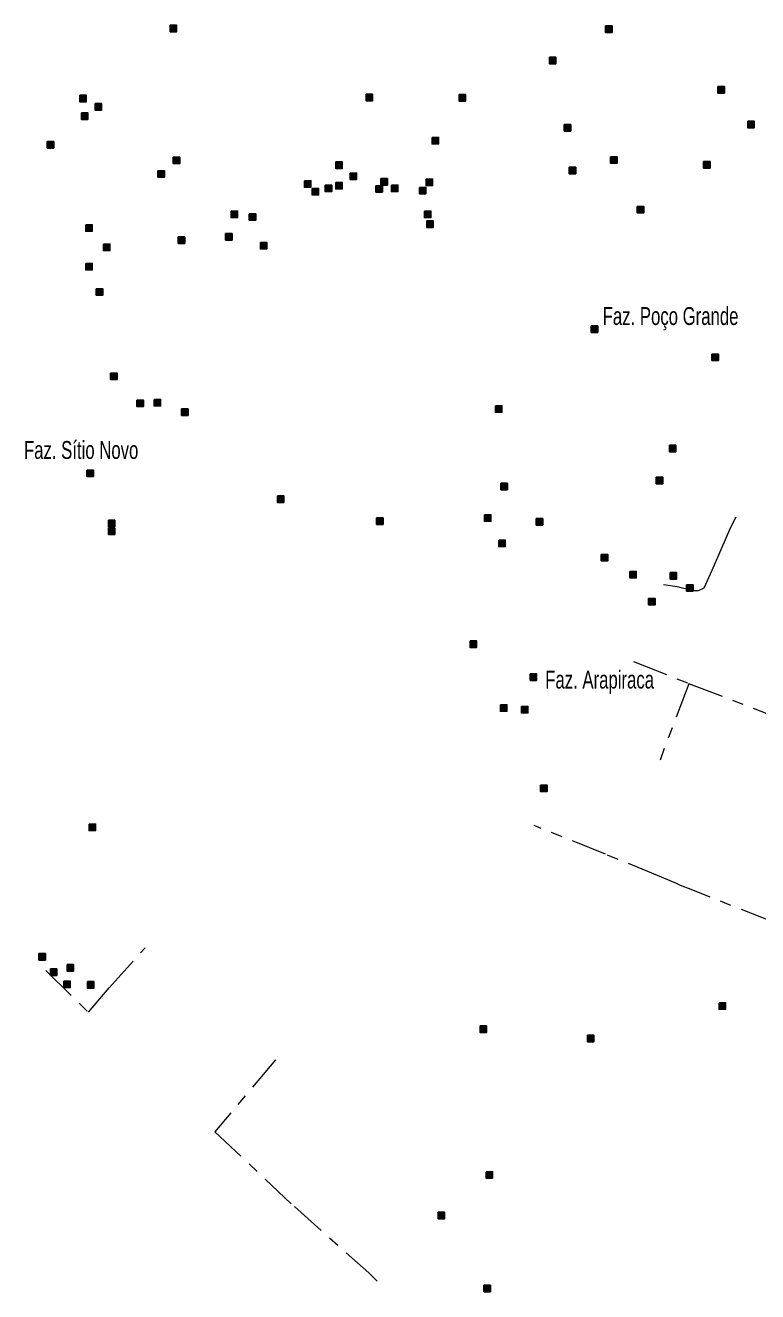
# Model space of a CAD drawing. Extents: x 445.4 to 500, y 8728.7 to 8784.
# Drawn here: x 486.04 to 492.59, y 8746.28 to 8757.61 of the extents above; entities that cross this region are included whole.
import ezdxf

# ---------------------------------------------------------------- set-up
doc = ezdxf.new("R2010")
doc.units = 0
doc.header["$LTSCALE"] = 0.064
doc.linetypes.add('DOT_DASHED', pattern=[7.7, 5, -1.2, 0.3, -1.2])
doc.layers.add('2', color=7, linetype='Continuous', lineweight=25)
doc.layers.add('22', color=7, linetype='DOT_DASHED', lineweight=13)
doc.layers.add('61', color=7, linetype='Continuous')

msp = doc.modelspace()

# ---------------------------------------------------------------- hatches: boundary and pattern name
at = {"layer": '2'}
for points in [[(487.3313, 8757.6084), (487.3893, 8757.6084), (487.3893, 8757.5504), (487.3313, 8757.5504)], [(491.2303, 8757.6032), (491.2883, 8757.6032), (491.2883, 8757.5452), (491.2303, 8757.5452)], [(490.7276, 8757.3221), (490.7856, 8757.3221), (490.7856, 8757.2641), (490.7276, 8757.2641)], [(492.2359, 8757.0607), (492.2939, 8757.0607), (492.2939, 8757.0027), (492.2359, 8757.0027)], [(486.5229, 8756.9821), (486.5809, 8756.9821), (486.5809, 8756.9241), (486.5229, 8756.9241)], [(486.6609, 8756.9081), (486.7189, 8756.9081), (486.7189, 8756.8501), (486.6609, 8756.8501)], [(489.0861, 8756.9919), (489.1441, 8756.9919), (489.1441, 8756.9339), (489.0861, 8756.9339)], [(489.9192, 8756.9888), (489.9772, 8756.9888), (489.9772, 8756.9308), (489.9192, 8756.9308)], [(486.5377, 8756.8242), (486.5957, 8756.8242), (486.5957, 8756.7662), (486.5377, 8756.7662)], [(490.8606, 8756.7205), (490.9186, 8756.7205), (490.9186, 8756.6625), (490.8606, 8756.6625)], [(492.5021, 8756.7501), (492.5601, 8756.7501), (492.5601, 8756.6921), (492.5021, 8756.6921)], [(486.2321, 8756.5678), (486.2901, 8756.5678), (486.2901, 8756.5098), (486.2321, 8756.5098)], [(489.6776, 8756.605), (489.7356, 8756.605), (489.7356, 8756.547), (489.6776, 8756.547)], [(487.3609, 8756.4297), (487.4189, 8756.4297), (487.4189, 8756.3717), (487.3609, 8756.3717)], [(488.815, 8756.3853), (488.873, 8756.3853), (488.873, 8756.3273), (488.815, 8756.3273)], [(490.905, 8756.3387), (490.963, 8756.3387), (490.963, 8756.2807), (490.905, 8756.2807)], [(491.2747, 8756.4324), (491.3327, 8756.4324), (491.3327, 8756.3744), (491.2747, 8756.3744)], [(492.1075, 8756.3889), (492.1655, 8756.3889), (492.1655, 8756.3309), (492.1075, 8756.3309)], [(487.2228, 8756.3064), (487.2808, 8756.3064), (487.2808, 8756.2484), (487.2228, 8756.2484)], [(488.534, 8756.2176), (488.592, 8756.2176), (488.592, 8756.1596), (488.534, 8756.1596)], [(488.9431, 8756.2867), (489.0011, 8756.2867), (489.0011, 8756.2287), (488.9431, 8756.2287)], [(489.2192, 8756.2374), (489.2772, 8756.2374), (489.2772, 8756.1794), (489.2192, 8756.1794)], [(489.6234, 8756.2324), (489.6814, 8756.2324), (489.6814, 8756.1744), (489.6234, 8756.1744)], [(488.603, 8756.1486), (488.661, 8756.1486), (488.661, 8756.0906), (488.603, 8756.0906)], [(488.7213, 8756.1782), (488.7793, 8756.1782), (488.7793, 8756.1202), (488.7213, 8756.1202)], [(488.815, 8756.2028), (488.873, 8756.2028), (488.873, 8756.1448), (488.815, 8756.1448)], [(489.1748, 8756.1733), (489.2328, 8756.1733), (489.2328, 8756.1153), (489.1748, 8756.1153)], [(489.3128, 8756.1782), (489.3708, 8756.1782), (489.3708, 8756.1202), (489.3128, 8756.1202)], [(489.5642, 8756.1585), (489.6222, 8756.1585), (489.6222, 8756.1005), (489.5642, 8756.1005)], [(487.8784, 8755.9464), (487.9364, 8755.9464), (487.9364, 8755.8884), (487.8784, 8755.8884)], [(488.0411, 8755.9217), (488.0991, 8755.9217), (488.0991, 8755.8637), (488.0411, 8755.8637)], [(489.6086, 8755.9464), (489.6666, 8755.9464), (489.6666, 8755.8884), (489.6086, 8755.8884)], [(491.514, 8755.9878), (491.572, 8755.9878), (491.572, 8755.9298), (491.514, 8755.9298)], [(486.5771, 8755.8231), (486.6351, 8755.8231), (486.6351, 8755.7651), (486.5771, 8755.7651)], [(489.6299, 8755.8576), (489.6879, 8755.8576), (489.6879, 8755.7996), (489.6299, 8755.7996)], [(486.7348, 8755.6505), (486.7928, 8755.6505), (486.7928, 8755.5925), (486.7348, 8755.5925)], [(487.4052, 8755.7146), (487.4632, 8755.7146), (487.4632, 8755.6566), (487.4052, 8755.6566)], [(487.8291, 8755.7442), (487.8871, 8755.7442), (487.8871, 8755.6862), (487.8291, 8755.6862)], [(488.1397, 8755.6653), (488.1977, 8755.6653), (488.1977, 8755.6073), (488.1397, 8755.6073)], [(486.5771, 8755.4779), (486.6351, 8755.4779), (486.6351, 8755.4199), (486.5771, 8755.4199)], [(486.6708, 8755.251), (486.7288, 8755.251), (486.7288, 8755.193), (486.6708, 8755.193)], [(491.1022, 8754.9184), (491.1602, 8754.9184), (491.1602, 8754.8604), (491.1022, 8754.8604)], [(492.1817, 8754.6669), (492.2397, 8754.6669), (492.2397, 8754.6089), (492.1817, 8754.6089)], [(486.7989, 8754.4965), (486.8569, 8754.4965), (486.8569, 8754.4385), (486.7989, 8754.4385)], [(487.0355, 8754.2548), (487.0935, 8754.2548), (487.0935, 8754.1968), (487.0355, 8754.1968)], [(487.1883, 8754.2598), (487.2463, 8754.2598), (487.2463, 8754.2018), (487.1883, 8754.2018)], [(487.4348, 8754.1759), (487.4928, 8754.1759), (487.4928, 8754.1179), (487.4348, 8754.1179)], [(490.2445, 8754.2033), (490.3025, 8754.2033), (490.3025, 8754.1453), (490.2445, 8754.1453)], [(491.8021, 8753.8502), (491.8601, 8753.8502), (491.8601, 8753.7922), (491.8021, 8753.7922)], [(486.587, 8753.6285), (486.645, 8753.6285), (486.645, 8753.5705), (486.587, 8753.5705)], [(490.2938, 8753.5099), (490.3518, 8753.5099), (490.3518, 8753.4519), (490.2938, 8753.4519)], [(491.6838, 8753.5642), (491.7418, 8753.5642), (491.7418, 8753.5062), (491.6838, 8753.5062)], [(488.2925, 8753.3967), (488.3505, 8753.3967), (488.3505, 8753.3387), (488.2925, 8753.3387)], [(486.7792, 8753.1797), (486.8372, 8753.1797), (486.8372, 8753.1217), (486.7792, 8753.1217)], [(489.1798, 8753.1994), (489.2378, 8753.1994), (489.2378, 8753.1414), (489.1798, 8753.1414)], [(490.1459, 8753.2288), (490.2039, 8753.2288), (490.2039, 8753.1708), (490.1459, 8753.1708)], [(490.6093, 8753.1943), (490.6673, 8753.1943), (490.6673, 8753.1363), (490.6093, 8753.1363)], [(486.7792, 8753.1107), (486.8372, 8753.1107), (486.8372, 8753.0527), (486.7792, 8753.0527)], [(490.2742, 8753.0011), (490.3322, 8753.0011), (490.3322, 8752.9431), (490.2742, 8752.9431)], [(491.1909, 8752.8737), (491.2489, 8752.8737), (491.2489, 8752.8157), (491.1909, 8752.8157)], [(491.4472, 8752.7208), (491.5052, 8752.7208), (491.5052, 8752.6628), (491.4472, 8752.6628)], [(491.8071, 8752.711), (491.8651, 8752.711), (491.8651, 8752.653), (491.8071, 8752.653)], [(491.9549, 8752.6025), (492.0129, 8752.6025), (492.0129, 8752.5445), (491.9549, 8752.5445)], [(491.6148, 8752.4792), (491.6728, 8752.4792), (491.6728, 8752.4212), (491.6148, 8752.4212)], [(490.0177, 8752.0995), (490.0757, 8752.0995), (490.0757, 8752.0415), (490.0177, 8752.0415)], [(490.555, 8751.8036), (490.613, 8751.8036), (490.613, 8751.7456), (490.555, 8751.7456)], [(490.2889, 8751.5274), (490.3469, 8751.5274), (490.3469, 8751.4694), (490.2889, 8751.4694)], [(490.4762, 8751.5126), (490.5342, 8751.5126), (490.5342, 8751.4546), (490.4762, 8751.4546)], [(490.6487, 8750.8094), (490.7067, 8750.8094), (490.7067, 8750.7514), (490.6487, 8750.7514)], [(486.6067, 8750.4603), (486.6647, 8750.4603), (486.6647, 8750.4023), (486.6067, 8750.4023)], [(486.1581, 8749.3014), (486.2161, 8749.3014), (486.2161, 8749.2434), (486.1581, 8749.2434)], [(486.4095, 8749.2028), (486.4675, 8749.2028), (486.4675, 8749.1448), (486.4095, 8749.1448)], [(486.2616, 8749.1633), (486.3196, 8749.1633), (486.3196, 8749.1053), (486.2616, 8749.1053)], [(486.3799, 8749.0548), (486.4379, 8749.0548), (486.4379, 8748.9968), (486.3799, 8748.9968)], [(486.5919, 8749.0499), (486.6499, 8749.0499), (486.6499, 8748.9919), (486.5919, 8748.9919)], [(492.2458, 8748.8613), (492.3038, 8748.8613), (492.3038, 8748.8033), (492.2458, 8748.8033)], [(490.1065, 8748.6542), (490.1645, 8748.6542), (490.1645, 8748.5962), (490.1065, 8748.5962)], [(491.0677, 8748.5704), (491.1257, 8748.5704), (491.1257, 8748.5124), (491.0677, 8748.5124)], [(490.1607, 8747.3493), (490.2187, 8747.3493), (490.2187, 8747.2913), (490.1607, 8747.2913)], [(489.731, 8746.9857), (489.789, 8746.9857), (489.789, 8746.9277), (489.731, 8746.9277)], [(490.141, 8746.3334), (490.199, 8746.3334), (490.199, 8746.2754), (490.141, 8746.2754)]]:
    msp.add_hatch(color=256, dxfattribs=at).paths.add_polyline_path(points)

# ---------------------------------------------------------------- linework, layer by layer
for points in [[(487.3313, 8757.6084), (487.3893, 8757.6084), (487.3893, 8757.5504), (487.3313, 8757.5504)], [(491.2303, 8757.6032), (491.2883, 8757.6032), (491.2883, 8757.5452), (491.2303, 8757.5452)], [(490.7276, 8757.3221), (490.7856, 8757.3221), (490.7856, 8757.2641), (490.7276, 8757.2641)], [(492.2359, 8757.0607), (492.2939, 8757.0607), (492.2939, 8757.0027), (492.2359, 8757.0027)], [(486.5229, 8756.9821), (486.5809, 8756.9821), (486.5809, 8756.9241), (486.5229, 8756.9241)], [(486.6609, 8756.9081), (486.7189, 8756.9081), (486.7189, 8756.8501), (486.6609, 8756.8501)], [(489.0861, 8756.9919), (489.1441, 8756.9919), (489.1441, 8756.9339), (489.0861, 8756.9339)], [(489.9192, 8756.9888), (489.9772, 8756.9888), (489.9772, 8756.9308), (489.9192, 8756.9308)], [(486.5377, 8756.8242), (486.5957, 8756.8242), (486.5957, 8756.7662), (486.5377, 8756.7662)], [(490.8606, 8756.7205), (490.9186, 8756.7205), (490.9186, 8756.6625), (490.8606, 8756.6625)], [(492.5021, 8756.7501), (492.5601, 8756.7501), (492.5601, 8756.6921), (492.5021, 8756.6921)], [(486.2321, 8756.5678), (486.2901, 8756.5678), (486.2901, 8756.5098), (486.2321, 8756.5098)], [(489.6776, 8756.605), (489.7356, 8756.605), (489.7356, 8756.547), (489.6776, 8756.547)], [(487.3609, 8756.4297), (487.4189, 8756.4297), (487.4189, 8756.3717), (487.3609, 8756.3717)], [(488.815, 8756.3853), (488.873, 8756.3853), (488.873, 8756.3273), (488.815, 8756.3273)], [(490.905, 8756.3387), (490.963, 8756.3387), (490.963, 8756.2807), (490.905, 8756.2807)], [(491.2747, 8756.4324), (491.3327, 8756.4324), (491.3327, 8756.3744), (491.2747, 8756.3744)], [(492.1075, 8756.3889), (492.1655, 8756.3889), (492.1655, 8756.3309), (492.1075, 8756.3309)], [(487.2228, 8756.3064), (487.2808, 8756.3064), (487.2808, 8756.2484), (487.2228, 8756.2484)], [(488.534, 8756.2176), (488.592, 8756.2176), (488.592, 8756.1596), (488.534, 8756.1596)], [(488.9431, 8756.2867), (489.0011, 8756.2867), (489.0011, 8756.2287), (488.9431, 8756.2287)], [(489.2192, 8756.2374), (489.2772, 8756.2374), (489.2772, 8756.1794), (489.2192, 8756.1794)], [(489.6234, 8756.2324), (489.6814, 8756.2324), (489.6814, 8756.1744), (489.6234, 8756.1744)], [(488.603, 8756.1486), (488.661, 8756.1486), (488.661, 8756.0906), (488.603, 8756.0906)], [(488.7213, 8756.1782), (488.7793, 8756.1782), (488.7793, 8756.1202), (488.7213, 8756.1202)], [(488.815, 8756.2028), (488.873, 8756.2028), (488.873, 8756.1448), (488.815, 8756.1448)], [(489.1748, 8756.1733), (489.2328, 8756.1733), (489.2328, 8756.1153), (489.1748, 8756.1153)], [(489.3128, 8756.1782), (489.3708, 8756.1782), (489.3708, 8756.1202), (489.3128, 8756.1202)], [(489.5642, 8756.1585), (489.6222, 8756.1585), (489.6222, 8756.1005), (489.5642, 8756.1005)], [(487.8784, 8755.9464), (487.9364, 8755.9464), (487.9364, 8755.8884), (487.8784, 8755.8884)], [(488.0411, 8755.9217), (488.0991, 8755.9217), (488.0991, 8755.8637), (488.0411, 8755.8637)], [(489.6086, 8755.9464), (489.6666, 8755.9464), (489.6666, 8755.8884), (489.6086, 8755.8884)], [(491.514, 8755.9878), (491.572, 8755.9878), (491.572, 8755.9298), (491.514, 8755.9298)], [(486.5771, 8755.8231), (486.6351, 8755.8231), (486.6351, 8755.7651), (486.5771, 8755.7651)], [(489.6299, 8755.8576), (489.6879, 8755.8576), (489.6879, 8755.7996), (489.6299, 8755.7996)], [(486.7348, 8755.6505), (486.7928, 8755.6505), (486.7928, 8755.5925), (486.7348, 8755.5925)], [(487.4052, 8755.7146), (487.4632, 8755.7146), (487.4632, 8755.6566), (487.4052, 8755.6566)], [(487.8291, 8755.7442), (487.8871, 8755.7442), (487.8871, 8755.6862), (487.8291, 8755.6862)], [(488.1397, 8755.6653), (488.1977, 8755.6653), (488.1977, 8755.6073), (488.1397, 8755.6073)], [(486.5771, 8755.4779), (486.6351, 8755.4779), (486.6351, 8755.4199), (486.5771, 8755.4199)], [(486.6708, 8755.251), (486.7288, 8755.251), (486.7288, 8755.193), (486.6708, 8755.193)], [(491.1022, 8754.9184), (491.1602, 8754.9184), (491.1602, 8754.8604), (491.1022, 8754.8604)], [(492.1817, 8754.6669), (492.2397, 8754.6669), (492.2397, 8754.6089), (492.1817, 8754.6089)], [(486.7989, 8754.4965), (486.8569, 8754.4965), (486.8569, 8754.4385), (486.7989, 8754.4385)], [(487.0355, 8754.2548), (487.0935, 8754.2548), (487.0935, 8754.1968), (487.0355, 8754.1968)], [(487.1883, 8754.2598), (487.2463, 8754.2598), (487.2463, 8754.2018), (487.1883, 8754.2018)], [(487.4348, 8754.1759), (487.4928, 8754.1759), (487.4928, 8754.1179), (487.4348, 8754.1179)], [(490.2445, 8754.2033), (490.3025, 8754.2033), (490.3025, 8754.1453), (490.2445, 8754.1453)], [(491.8021, 8753.8502), (491.8601, 8753.8502), (491.8601, 8753.7922), (491.8021, 8753.7922)], [(486.587, 8753.6285), (486.645, 8753.6285), (486.645, 8753.5705), (486.587, 8753.5705)], [(490.2938, 8753.5099), (490.3518, 8753.5099), (490.3518, 8753.4519), (490.2938, 8753.4519)], [(491.6838, 8753.5642), (491.7418, 8753.5642), (491.7418, 8753.5062), (491.6838, 8753.5062)], [(488.2925, 8753.3967), (488.3505, 8753.3967), (488.3505, 8753.3387), (488.2925, 8753.3387)], [(486.7792, 8753.1797), (486.8372, 8753.1797), (486.8372, 8753.1217), (486.7792, 8753.1217)], [(489.1798, 8753.1994), (489.2378, 8753.1994), (489.2378, 8753.1414), (489.1798, 8753.1414)], [(490.1459, 8753.2288), (490.2039, 8753.2288), (490.2039, 8753.1708), (490.1459, 8753.1708)], [(490.6093, 8753.1943), (490.6673, 8753.1943), (490.6673, 8753.1363), (490.6093, 8753.1363)], [(486.7792, 8753.1107), (486.8372, 8753.1107), (486.8372, 8753.0527), (486.7792, 8753.0527)], [(490.2742, 8753.0011), (490.3322, 8753.0011), (490.3322, 8752.9431), (490.2742, 8752.9431)], [(491.1909, 8752.8737), (491.2489, 8752.8737), (491.2489, 8752.8157), (491.1909, 8752.8157)], [(491.4472, 8752.7208), (491.5052, 8752.7208), (491.5052, 8752.6628), (491.4472, 8752.6628)], [(491.8071, 8752.711), (491.8651, 8752.711), (491.8651, 8752.653), (491.8071, 8752.653)], [(491.9549, 8752.6025), (492.0129, 8752.6025), (492.0129, 8752.5445), (491.9549, 8752.5445)], [(491.6148, 8752.4792), (491.6728, 8752.4792), (491.6728, 8752.4212), (491.6148, 8752.4212)], [(490.0177, 8752.0995), (490.0757, 8752.0995), (490.0757, 8752.0415), (490.0177, 8752.0415)], [(490.555, 8751.8036), (490.613, 8751.8036), (490.613, 8751.7456), (490.555, 8751.7456)], [(490.2889, 8751.5274), (490.3469, 8751.5274), (490.3469, 8751.4694), (490.2889, 8751.4694)], [(490.4762, 8751.5126), (490.5342, 8751.5126), (490.5342, 8751.4546), (490.4762, 8751.4546)], [(490.6487, 8750.8094), (490.7067, 8750.8094), (490.7067, 8750.7514), (490.6487, 8750.7514)], [(486.6067, 8750.4603), (486.6647, 8750.4603), (486.6647, 8750.4023), (486.6067, 8750.4023)], [(486.1581, 8749.3014), (486.2161, 8749.3014), (486.2161, 8749.2434), (486.1581, 8749.2434)], [(486.4095, 8749.2028), (486.4675, 8749.2028), (486.4675, 8749.1448), (486.4095, 8749.1448)], [(486.2616, 8749.1633), (486.3196, 8749.1633), (486.3196, 8749.1053), (486.2616, 8749.1053)], [(486.3799, 8749.0548), (486.4379, 8749.0548), (486.4379, 8748.9968), (486.3799, 8748.9968)], [(486.5919, 8749.0499), (486.6499, 8749.0499), (486.6499, 8748.9919), (486.5919, 8748.9919)], [(492.2458, 8748.8613), (492.3038, 8748.8613), (492.3038, 8748.8033), (492.2458, 8748.8033)], [(490.1065, 8748.6542), (490.1645, 8748.6542), (490.1645, 8748.5962), (490.1065, 8748.5962)], [(491.0677, 8748.5704), (491.1257, 8748.5704), (491.1257, 8748.5124), (491.0677, 8748.5124)], [(490.1607, 8747.3493), (490.2187, 8747.3493), (490.2187, 8747.2913), (490.1607, 8747.2913)], [(489.731, 8746.9857), (489.789, 8746.9857), (489.789, 8746.9277), (489.731, 8746.9277)], [(490.141, 8746.3334), (490.199, 8746.3334), (490.199, 8746.2754), (490.141, 8746.2754)]]:
    msp.add_lwpolyline(points, close=True, dxfattribs=at)
at = {"layer": '22'}
msp.add_line((491.9744, 8751.7153), (491.7171, 8751.0322), dxfattribs=at)
for points in [[(491.7494, 8752.6036), (491.871, 8752.5862), (492.0157, 8752.5494), (492.062, 8752.5513), (492.1122, 8752.5746), (492.1836, 8752.7333), (492.2723, 8752.9384), (492.3418, 8753.0952), (492.3881, 8753.19), (492.3997, 8753.2093)], [(491.4786, 8751.9154), (491.9736, 8751.7188), (492.7571, 8751.4183), (493.1361, 8751.2616)], [(493.1177, 8751.0897), (493.0549, 8750.3687), (493.0391, 8750.1694), (493.2494, 8749.8272), (493.0772, 8749.4422), (493.0086, 8749.4374), (492.929, 8749.4764), (492.8412, 8749.5317), (492.7432, 8749.5783), (491.9959, 8749.8735), (491.9016, 8749.9117), (491.8634, 8749.9297), (491.7302, 8749.9859), (491.2298, 8750.1898), (490.5897, 8750.4468)], [(486.2182, 8749.1498), (486.6004, 8748.7774), (486.7866, 8748.994), (487.1079, 8749.3514)], [(488.2747, 8748.3488), (487.7328, 8747.7073), (488.4443, 8747.0362), (489.1097, 8746.444), (489.1844, 8746.37)]]:
    msp.add_lwpolyline(points, dxfattribs=at)

# ---------------------------------------------------------------- texts
at = {"layer": '61', "width": 0.7}
for s, p in [('Faz. Poço Grande', (491.204, 8754.9267)), ('Faz. Sítio Novo', (486.0238, 8753.7281)), ('Faz. Arapiraca', (490.6897, 8751.673))]:
    msp.add_text(s, height=0.16, dxfattribs=at).set_placement(p)

doc.saveas('drawing.dxf')
